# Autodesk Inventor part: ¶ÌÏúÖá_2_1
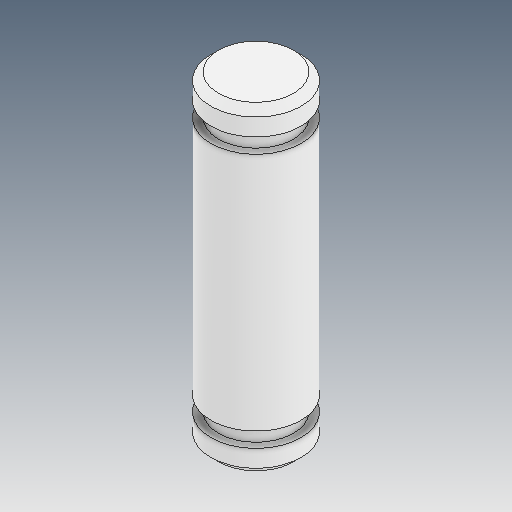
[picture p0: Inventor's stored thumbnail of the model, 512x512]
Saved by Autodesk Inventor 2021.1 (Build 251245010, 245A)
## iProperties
Created: 2021-05
Part Number: ¶ÌÏúÖá_2_1
Material: Ogólny
Document SubType Name: Modeling
Designer: user
Density: 1 g/cm^3
Appearance: Domyślna
Author: user
Revision Number: ÈÎºÎ
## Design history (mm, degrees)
feature "ÊäÈë1"
node "Bryła1"
